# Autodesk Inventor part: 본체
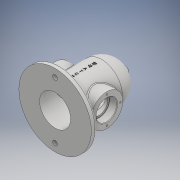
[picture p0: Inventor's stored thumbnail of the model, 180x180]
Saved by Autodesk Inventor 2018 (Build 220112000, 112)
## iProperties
Created: 2019-11
Part Number: 본체
Material: Generic
Document SubType Name: Modeling
Designer: Administrator
Density: 1 g/cm^3
Appearance: Default
Author: Administrator
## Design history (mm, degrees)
sketch "스케치1"
  geometry: C1 r 70 at (0, 0); 1 further point
  constraints: 1 centre point, 1 coincident
  dimensions: "d0" = 140 diameter of C1
extrude "돌출1" new body sketch "스케치1" distance "d1" = 10; taper "d2" = 0 deg
sketch "스케치2"
  geometry: C1 r 40 at (0, 0); 1 further point
  constraints: 1 centre point, 1 coincident
  dimensions: "d3" = 80 diameter of C1
extrude "돌출2" join sketch "스케치2" distance "d4" = 80; taper "d5" = 0 deg
sketch "스케치4"
  geometry: L1 (40, 90)-(-40, 90) reference; L2 (-40, 90)-(0, 90); L3 (0, 130)-(0, 90); A1 r 40 centre (0, 90) between (0, 130) and (-40, 90); 1 further point
  constraints: 4 end point, 2 point on circle, 1 centre point, 1 collinear, 1 midpoint, 1 vertical
revolve "회전1" sketch "스케치4" stored, may be unused: angle "d6" = 360 deg
sketch "스케치5"
  geometry: C1 r 30 at (0, 0); 1 further point
  constraints: 1 centre point, 1 coincident
  dimensions: "d7" = 60 diameter of C1
extrude "돌출3" cut sketch "스케치5" distance "d8" = 90; taper "d9" = 0 deg
sketch "스케치6"
  geometry: L1 (30, 90)-(-30, 90) reference; L2 (-30, 90)-(0, 90); L3 (0, 90)-(0, 120); A1 r 30 centre (0, 90) between (0, 120) and (-30, 90); 1 further point
  constraints: 4 end point, 2 point on circle, 1 centre point, 1 collinear, 1 midpoint, 1 vertical
revolve "회전2" sketch "스케치6" stored, may be unused: angle "d10" = 360 deg
sketch "스케치7"
  geometry: C1 r 31 at (50, 0); 1 further point
  constraints: 1 centre point
  dimensions: "d12" = 62 diameter of C1
extrude "돌출4" join sketch "스케치7" stored distance "d13" = 100; taper "d14" = 0 deg
sketch "스케치8"
  geometry: C1 r 30 at (0, 0); 1 further point
  constraints: 1 centre point, 1 coincident
extrude "돌출5" cut sketch "스케치8" distance "d15" = 90; taper "d16" = 0 deg
sketch "스케치9"
  geometry: C1 r 20 at (0, 0); 1 further point
  constraints: 1 centre point
  dimensions: "d17" = 40 diameter of C1
extrude "돌출6" cut sketch "스케치9" distance "d18" = 15; taper "d19" = 0 deg
sketch "스케치10"
  geometry: C1 r 20 at (0, 0); 1 further point
  constraints: 1 centre point
  dimensions: "d20" = 40 diameter of C1
extrude "돌출7" cut sketch "스케치10" distance "d21" = 15; taper "d22" = 0 deg
sketch "스케치11"
  geometry: C1 r 16.5 at (0, 0); 1 further point
  constraints: 1 centre point
  dimensions: "d23" = 33 diameter of C1
extrude "돌출8" cut sketch "스케치11" extent not by distance; stored distance "d24" = 15; taper "d25" = 0 deg
fillet "모깎기1" dims "d26" = 0.3
sketch "스케치13"
  geometry: C1 r 7.5 at (0, 0); 1 further point
  constraints: 1 centre point, 1 coincident
  dimensions: "d27" = 15 diameter of C1
extrude "돌출9" join sketch "스케치13" distance "d28" = 135; taper "d29" = 0 deg
sketch "스케치14"
  geometry: C1 r 7.5 at (0, 0); 1 further point
  constraints: 1 centre point, 1 coincident
extrude "돌출10" cut sketch "스케치14" distance "d30" = 90; taper "d31" = 0 deg
sketch "스케치15"
  geometry: L1 (30, 90)-(-30, 90) reference; L2 (-30, 90)-(0, 90); L3 (7.5, 90)-(-7.5, 90) reference; L4 (7.5, 119.047)-(-7.5, 119.047) reference; L5 (0, 120)-(0, 90); A1 r 30 centre (0, 90) between (0, 120) and (-30, 90); 1 further point
  constraints: 5 end point, 2 point on circle, 1 centre point, 1 collinear, 1 midpoint, 1 perpendicular
revolve "회전3" sketch "스케치15" stored, may be unused: angle "d32" = 360 deg
sketch "스케치16"
  geometry: 1 further point
sketch "스케치17"
  geometry: C1 r 7.5 at (0, 0) reference; C2 r 3 at (0, 0); 1 further point
  constraints: 1 centre point, 1 coincident
  dimensions: "d33" = 6 diameter of C2
extrude "돌출11" cut sketch "스케치17" distance "d34" = 90; taper "d35" = 0 deg
feature "스레드1" dims "d36" = 10, "d37" = 0
sketch "스케치18"
  geometry: 5 further points
hole "구멍1" sketch "스케치18" at (0, 26), (-26, 0), (0, -26), (26, 0) diameter "d39" = 3.242; stored, may be unused: countersink angle "d43" = 90 deg, drill point angle "d45" = 118 deg; dims "d40" = 8, "d41" = 4, "d42" = 2, "d44" = 10
fillet "모깎기2" dims "d46" = 3
sketch "스케치19"
  geometry: C1 r 4.5 at (0, 55); C2 r 4.5 at (0, -55); A1 r 55 centre (0, 0) between (0, 55) and (0, -55); 1 further point
  constraints: 3 centre point, 2 point on circle, 1 coincident
  dimensions: "d47" = 110 diameter of A1; "d48" = 9 diameter of C1; "d49" = 9 diameter of C2
extrude "돌출12" cut sketch "스케치19" distance "d50" = 90; taper "d51" = 0 deg
fillet "모깎기3" dims "d52" = 3
node "작업 평면2"
sketch "스케치24"
  geometry: L1 (-40, 13)-(40, 13); L2 (30, 90)-(-30, 90); L3 (-70, 0)-(70, 0); 2 further points
  constraints: 6 end point, 1 other
feature "엠보싱1" sketch "스케치24" dims "d2" = 0, "d8" = 90, "d9" = 0, "d60" = 0.5, "d61" = 0
chamfer "모따기1" distance "d62" = 1; stored, may be unused: second distance "d63" = 2, angle "d64" = 45 deg
node "솔리드1"
mirror "미러1"
